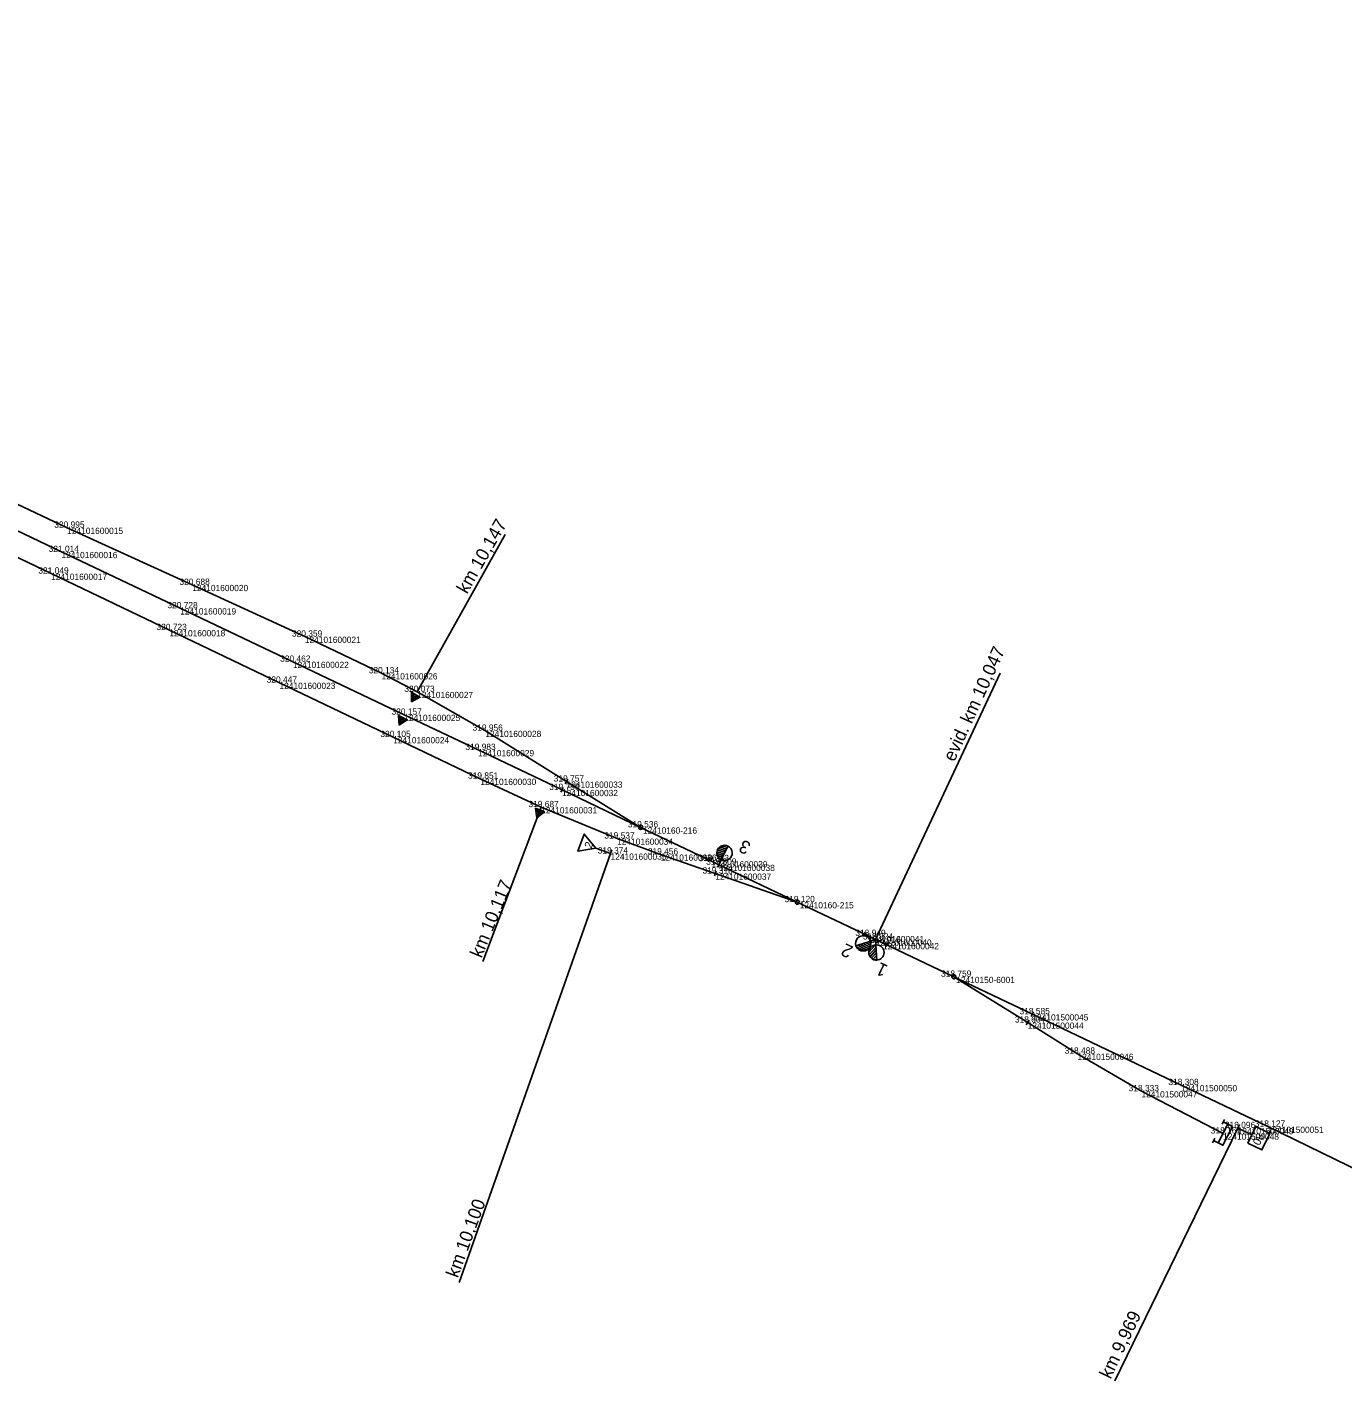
# Model space of a CAD drawing. Extents: x -616949 to -607976, y -1164436 to -1159224.
# Drawn here: x -616071.3 to -615819.4, y -1159974.5 to -1159715.2 of the extents above; entities that cross this region are included whole.
import ezdxf

# ---------------------------------------------------------------- set-up
doc = ezdxf.new("R2010")
doc.units = 0
for name, color, linetype in [('Vrstva 1', 7, 'Continuous'), ('Vrstva 15', 7, 'Continuous'), ('Vrstva 2', 7, 'Continuous'), ('Vrstva 3', 7, 'Continuous'), ('Vrstva 5', 7, 'Continuous'), ('Vrstva 60', 7, 'Continuous'), ('Vrstva 61', 7, 'Continuous')]:
    doc.layers.add(name, color=color, linetype=linetype)

msp = doc.modelspace()

# ---------------------------------------------------------------- linework, layer by layer
at = {"layer": 'Vrstva 1'}
for points in [[(-615908.84, -1159889.93), (-615910.27, -1159889.25), (-615923.84, -1159882.78), (-615939.55, -1159877.3), (-615950.02, -1159873.65), (-615958.35, -1159870.6), (-615972.88, -1159864.59), (-615984.54, -1159859.14), (-616001.22, -1159851.17), (-616023, -1159840.76), (-616044.09, -1159830.68), (-616066.72, -1159819.87), (-616088.67, -1159809.39), (-616107.11, -1159800.11), (-616112.99, -1159796.93), (-616128.47, -1159787.95), (-616137.63, -1159782.18), (-616142.77, -1159778.79), (-616153.3, -1159771.43), (-616169.07, -1159759.51), (-616184.52, -1159746.63), (-616200.28, -1159732.04), (-616217.13, -1159716.1), (-616218.05, -1159715.21)], [(-615938.86, -1159875.61), (-615940.27, -1159874.93), (-615953.84, -1159868.46), (-615968.03, -1159859.68), (-615983.58, -1159849.96), (-615996.64, -1159842.51), (-616003.45, -1159838.94), (-616018.15, -1159831.94), (-616039.7, -1159822.03), (-616063.66, -1159811.08), (-616084.21, -1159801.41), (-616107.46, -1159789.34), (-616114.32, -1159785.46), (-616128.35, -1159776.94), (-616131.48, -1159774.93), (-616137.2, -1159771.16), (-616148.09, -1159763.54), (-616163.09, -1159752.06), (-616177.88, -1159739.63), (-616193.93, -1159724.96), (-616196.14, -1159722.89)], [(-615938.86, -1159875.61), (-615940.27, -1159874.93), (-615953.84, -1159868.46), (-615968.9, -1159861.28), (-615984.95, -1159853.64), (-615999.1, -1159846.89), (-616020.43, -1159836.75), (-616042.01, -1159826.5), (-616064.75, -1159815.71), (-616086.42, -1159805.34)], [(-615908.84, -1159889.93), (-615910.27, -1159889.25), (-615923.84, -1159882.78), (-615938.86, -1159875.61)], [(-615842.33, -1159927.08), (-615857.95, -1159918.98), (-615870.19, -1159911.8), (-615879.73, -1159905.83), (-615893.87, -1159897.07), (-615907.43, -1159890.61), (-615908.84, -1159889.93)], [(-615813.21, -1159935.78), (-615833.77, -1159925.77), (-615850.34, -1159917.81), (-615878.83, -1159904.24), (-615893.87, -1159897.07), (-615907.43, -1159890.61), (-615908.84, -1159889.93)]]:
    msp.add_lwpolyline(points, dxfattribs=at)
at = {"layer": 'Vrstva 15'}
for p, q in [((-615841.41, -1159925.31), (-615843.25, -1159928.86)), ((-615842.06, -1159924.4), (-615842.52, -1159925.29)), ((-615843.91, -1159927.95), (-615844.37, -1159928.84))]:
    msp.add_line(p, q, dxfattribs=at)
msp.add_lwpolyline([(-615844.14, -1159928.4), (-615842.36, -1159929.32), (-615840.52, -1159925.77), (-615842.29, -1159924.85)], dxfattribs=at)
at = {"layer": 'Vrstva 2'}
for p, q in [((-615908.84, -1159889.93), (-615885.02, -1159838.94)), ((-615968.29, -1159860.1), (-615967.76, -1159859.26)), ((-615953.84, -1159868.46), (-615968.03, -1159859.68)), ((-615968.68, -1159860.83), (-615969.12, -1159861.73)), ((-615939.24, -1159873.44), (-615937.54, -1159872.84)), ((-615939.21, -1159873.03), (-615937.31, -1159872.35)), ((-615939.17, -1159873.82), (-615937.77, -1159873.32)), ((-615939.01, -1159872.55), (-615937.34, -1159871.96)), ((-615938.41, -1159874.67), (-615937.15, -1159872.03)), ((-615939.07, -1159876.06), (-615938.64, -1159875.16)), ((-615939, -1159874.16), (-615938, -1159873.81)), ((-615938.41, -1159874.67), (-615938.86, -1159875.61)), ((-615938.72, -1159874.47), (-615938.23, -1159874.29)), ((-615939.71, -1159877.77), (-615939.38, -1159876.82)), ((-615909.83, -1159890.24), (-615912.63, -1159891.12)), ((-615910.98, -1159892.12), (-615912.55, -1159891.31)), ((-615910.5, -1159891.95), (-615912.28, -1159891.02)), ((-615910.17, -1159891.69), (-615911.77, -1159890.86)), ((-615909.94, -1159891.38), (-615911.26, -1159890.69)), ((-615909.81, -1159891.02), (-615910.75, -1159890.53)), ((-615909.77, -1159890.61), (-615910.23, -1159890.37)), ((-615908.89, -1159890.97), (-615910.15, -1159892.39)), ((-615908.75, -1159891.38), (-615910.08, -1159892.88)), ((-615909.83, -1159890.24), (-615908.84, -1159889.93)), ((-615908.78, -1159890.96), (-615908.84, -1159889.93)), ((-615908.6, -1159893.88), (-615908.78, -1159890.96)), ((-615908.72, -1159891.91), (-615909.9, -1159893.24)), ((-615908.69, -1159892.44), (-615909.64, -1159893.52)), ((-615908.66, -1159892.97), (-615909.33, -1159893.73)), ((-615908.62, -1159893.5), (-615908.94, -1159893.85)), ((-615893.87, -1159897.07), (-615879.73, -1159905.83)), ((-615879.05, -1159904.69), (-615878.62, -1159903.79)), ((-615880, -1159906.25), (-615879.47, -1159905.41))]:
    msp.add_line(p, q, dxfattribs=at)
for points in [[(-615938.86, -1159875.61), (-615940.27, -1159874.93), (-615953.84, -1159868.46), (-615968.9, -1159861.28)], [(-615941.26, -1159874.75), (-615940.27, -1159874.93), (-615941.03, -1159874.28)], [(-615908.84, -1159889.93), (-615910.27, -1159889.25), (-615923.84, -1159882.78), (-615938.86, -1159875.61)], [(-615923.84, -1159882.78), (-615939.55, -1159877.3)], [(-615911.26, -1159889.06), (-615910.27, -1159889.25), (-615911.03, -1159888.6)], [(-615908.84, -1159889.93), (-615907.43, -1159890.61), (-615893.87, -1159897.07), (-615878.83, -1159904.24)], [(-615906.45, -1159890.79), (-615907.43, -1159890.61), (-615906.68, -1159891.26)]]:
    msp.add_lwpolyline(points, dxfattribs=at)
for centre, radius in [((-615953.84, -1159868.46), 0.4), ((-615923.84, -1159882.78), 0.4), ((-615908.69, -1159892.42), 1.46), ((-615893.87, -1159897.07), 0.4)]:
    msp.add_circle(centre, radius, dxfattribs=at)
for centre, start, end in [((-615937.78, -1159873.35), 64.5185, 244.4794), ((-615937.77, -1159873.36), 244.2642, 64.7337), ((-615911.23, -1159890.68), 17.2943, 197.7638), ((-615911.23, -1159890.68), 197.5486, 17.5095), ((-615908.69, -1159892.42), 93.53, 273.4908)]:
    msp.add_arc(centre, 1.46, start, end, dxfattribs=at)
at = {"layer": 'Vrstva 3'}
for p, q in [((-615996.64, -1159842.51), (-615979.79, -1159812.35)), ((-615997.33, -1159842.82), (-615997.74, -1159842.93)), ((-615996.95, -1159843.04), (-615997.74, -1159843.25)), ((-615996.58, -1159843.25), (-615997.74, -1159843.57)), ((-615996.2, -1159843.47), (-615997.74, -1159843.89)), ((-615997.01, -1159844), (-615997.73, -1159844.21)), ((-615999.77, -1159847.25), (-616000.17, -1159847.4)), ((-615999.37, -1159847.44), (-616000.15, -1159847.72)), ((-615998.99, -1159847.63), (-616000.13, -1159848.03)), ((-615998.59, -1159847.82), (-616000.1, -1159848.35)), ((-615999.36, -1159848.41), (-616000.07, -1159848.67)), ((-615972.88, -1159864.59), (-615984.07, -1159894.16)), ((-615973.52, -1159864.99), (-615973.92, -1159865.15)), ((-615973.12, -1159865.15), (-615973.88, -1159865.47)), ((-615972.72, -1159865.32), (-615973.84, -1159865.78)), ((-615972.32, -1159865.49), (-615973.79, -1159866.1)), ((-615973.06, -1159866.12), (-615973.75, -1159866.41))]:
    msp.add_line(p, q, dxfattribs=at)
for points in [[(-615997.74, -1159844.43), (-615996.14, -1159843.5), (-615997.75, -1159842.58)], [(-616000.05, -1159848.89), (-615998.53, -1159847.85), (-616000.2, -1159847.05)], [(-615973.72, -1159866.64), (-615972.26, -1159865.51), (-615973.97, -1159864.8)]]:
    msp.add_lwpolyline(points, close=True, dxfattribs=at)
at = {"layer": 'Vrstva 5'}
for p, q in [((-615959.6, -1159873.47), (-615988.58, -1159955.59)), ((-615959.86, -1159874.18), (-615959.35, -1159872.77)), ((-615839.19, -1159925.36), (-615839.84, -1159926.71)), ((-615839.52, -1159926.04), (-615863.05, -1159974.46)), ((-615839.52, -1159926.04), (-615836.81, -1159927.34))]:
    msp.add_line(p, q, dxfattribs=at)
msp.add_lwpolyline([(-615959.6, -1159873.47), (-615962.42, -1159872.44), (-615965.84, -1159873.05), (-615964.64, -1159869.76), (-615962.42, -1159872.44)], dxfattribs=at)
msp.add_lwpolyline([(-615837.57, -1159928.91), (-615836.06, -1159925.76), (-615833.35, -1159927.06), (-615834.87, -1159930.21)], close=True, dxfattribs=at)
at = {"layer": 'Vrstva 60'}
for p, q in [((-616063.66, -1159811.08), (-616063.66, -1159811.08)), ((-616064.75, -1159815.71), (-616064.75, -1159815.71)), ((-616066.72, -1159819.87), (-616066.72, -1159819.87)), ((-616039.7, -1159822.03), (-616039.7, -1159822.03)), ((-616042.01, -1159826.5), (-616042.01, -1159826.5)), ((-616044.09, -1159830.68), (-616044.09, -1159830.68)), ((-616018.15, -1159831.94), (-616018.15, -1159831.94)), ((-616020.43, -1159836.75), (-616020.43, -1159836.75)), ((-616003.45, -1159838.94), (-616003.45, -1159838.94)), ((-616023, -1159840.76), (-616023, -1159840.76)), ((-615996.64, -1159842.51), (-615996.64, -1159842.51)), ((-615999.1, -1159846.89), (-615999.1, -1159846.89)), ((-615983.58, -1159849.96), (-615983.58, -1159849.96)), ((-616001.22, -1159851.17), (-616001.22, -1159851.17)), ((-615984.95, -1159853.64), (-615984.95, -1159853.64)), ((-615984.54, -1159859.14), (-615984.54, -1159859.14)), ((-615968.03, -1159859.68), (-615968.03, -1159859.68)), ((-615968.9, -1159861.28), (-615968.9, -1159861.28)), ((-615972.88, -1159864.59), (-615972.88, -1159864.59)), ((-615953.84, -1159868.46), (-615953.84, -1159868.46)), ((-615958.35, -1159870.6), (-615958.35, -1159870.6)), ((-615959.6, -1159873.47), (-615959.6, -1159873.47)), ((-615950.02, -1159873.65), (-615950.02, -1159873.65)), ((-615940.27, -1159874.93), (-615940.27, -1159874.93)), ((-615938.86, -1159875.61), (-615938.86, -1159875.61)), ((-615939.55, -1159877.3), (-615939.55, -1159877.3)), ((-615923.84, -1159882.78), (-615923.84, -1159882.78)), ((-615910.27, -1159889.25), (-615910.27, -1159889.25)), ((-615908.84, -1159889.93), (-615908.84, -1159889.93)), ((-615907.43, -1159890.61), (-615907.43, -1159890.61)), ((-615893.87, -1159897.07), (-615893.87, -1159897.07)), ((-615878.83, -1159904.24), (-615878.83, -1159904.24)), ((-615879.73, -1159905.83), (-615879.73, -1159905.83)), ((-615870.19, -1159911.8), (-615870.19, -1159911.8)), ((-615857.95, -1159918.98), (-615857.95, -1159918.98)), ((-615850.34, -1159917.81), (-615850.34, -1159917.81)), ((-615842.33, -1159927.08), (-615842.33, -1159927.08)), ((-615839.52, -1159926.04), (-615839.52, -1159926.04)), ((-615833.77, -1159925.77), (-615833.77, -1159925.77))]:
    msp.add_line(p, q, dxfattribs=at)

# ---------------------------------------------------------------- texts
at = {"layer": 'Vrstva 2'}
for s, rotation, p in [('evid. km 10,047', 65.5113, (-615893.78, -1159856.04)), ('3', 154.4989, (-615932.54, -1159871.54)), ('2', 154.2864, (-615912.96, -1159891.39)), ('1', 154.5131, (-615906.32, -1159895.01))]:
    msp.add_text(s, height=2.5, rotation=rotation, dxfattribs=at).set_placement(p)
at = {"layer": 'Vrstva 3'}
for s, rotation, p in [('km 10,147', 60.2977, (-615987.09, -1159823.9)), ('km 10,117', 67.5074, (-615984.33, -1159893.61))]:
    msp.add_text(s, height=2.5, rotation=rotation, dxfattribs=at).set_placement(p)
at = {"layer": 'Vrstva 5'}
for s, height, rotation, p in [('2', 1.5, 69.8718, (-615963.27, -1159872.59)), ('80', 1.5, 244.341, (-615835.74, -1159926.84)), ('km 10,100', 2.5, 69.8718, (-615988.86, -1159954.86)), ('km 9,969', 2.5, 64.341, (-615863.88, -1159974.22))]:
    msp.add_text(s, height=height, rotation=rotation, dxfattribs=at).set_placement(p)
at = {"layer": 'Vrstva 60'}
for s, p in [('124101600015', (-616063.66, -1159812.28)), ('124101600016', (-616064.75, -1159816.91)), ('124101600017', (-616066.72, -1159821.07)), ('124101600020', (-616039.7, -1159823.23)), ('124101600019', (-616042.01, -1159827.7)), ('124101600018', (-616044.09, -1159831.88)), ('124101600021', (-616018.15, -1159833.14)), ('124101600022', (-616020.43, -1159837.95)), ('124101600026', (-616003.45, -1159840.14)), ('124101600023', (-616023, -1159841.96)), ('124101600027', (-615996.64, -1159843.71)), ('124101600025', (-615999.1, -1159848.09)), ('124101600028', (-615983.58, -1159851.16)), ('124101600024', (-616001.22, -1159852.37)), ('124101600029', (-615984.95, -1159854.84)), ('124101600030', (-615984.54, -1159860.34)), ('124101600033', (-615968.03, -1159860.88)), ('124101600032', (-615968.9, -1159862.48)), ('124101600031', (-615972.88, -1159865.79)), (' 12410160-216', (-615953.84, -1159869.66)), ('124101600034', (-615958.35, -1159871.8)), ('124101600035', (-615959.6, -1159874.67)), ('124101600036', (-615950.02, -1159874.85)), ('124101600039', (-615940.27, -1159876.13)), ('124101600038', (-615938.86, -1159876.81)), ('124101600037', (-615939.55, -1159878.5)), (' 12410160-215', (-615923.84, -1159883.98)), ('124101600041', (-615910.27, -1159890.45)), ('124101600040', (-615908.84, -1159891.13)), ('124101600042', (-615907.43, -1159891.81)), (' 12410150-6001', (-615893.87, -1159898.28)), ('124101500045', (-615878.83, -1159905.44)), ('124101500044', (-615879.73, -1159907.03)), ('124101500046', (-615870.19, -1159913)), ('124101500047', (-615857.95, -1159920.18)), ('124101500050', (-615850.34, -1159919.01)), ('124101500048', (-615842.33, -1159928.28)), ('124101500049', (-615839.52, -1159927.24)), ('124101500051', (-615833.77, -1159926.97))]:
    msp.add_text(s, height=1.2, dxfattribs=at).set_placement(p)
at = {"layer": 'Vrstva 61'}
for s, p in [('320.995', (-616066.12, -1159811.08)), ('321.014', (-616067.2, -1159815.71)), ('321.049', (-616069.17, -1159819.87)), ('320.688', (-616042.15, -1159822.03)), ('320.728', (-616044.46, -1159826.5)), ('320.723', (-616046.55, -1159830.68)), ('320.359', (-616020.61, -1159831.94)), ('320.462', (-616022.87, -1159836.75)), ('320.447', (-616025.45, -1159840.76)), ('320.134', (-616005.91, -1159838.94)), ('320.073', (-615999.09, -1159842.51)), ('320.157', (-616001.55, -1159846.89)), ('320.105', (-616003.68, -1159851.17)), ('319.956', (-615986.03, -1159849.96)), ('319.983', (-615987.4, -1159853.64)), ('319.851', (-615986.9, -1159859.14)), ('319.750', (-615971.35, -1159861.28)), ('319.757', (-615970.48, -1159859.68)), ('319.687', (-615975.33, -1159864.59)), ('319.536', (-615956.29, -1159868.46)), ('319.537', (-615960.8, -1159870.6)), ('319.374', (-615962.06, -1159873.47)), ('319.456', (-615952.47, -1159873.65)), ('319.343', (-615942.73, -1159874.93)), ('319.318', (-615942, -1159877.3)), ('319.309', (-615941.31, -1159875.61)), ('319.120', (-615926.29, -1159882.78)), ('318.949', (-615912.73, -1159889.25)), ('318.924', (-615911.29, -1159889.93)), ('318.916', (-615909.89, -1159890.61)), ('318.759', (-615896.32, -1159897.07)), ('318.604', (-615882.18, -1159905.83)), ('318.585', (-615881.29, -1159904.24)), ('318.488', (-615872.64, -1159911.8)), ('318.308', (-615852.79, -1159917.81)), ('318.333', (-615860.4, -1159918.98)), ('318.096', (-615841.97, -1159926.04)), ('318.127', (-615836.22, -1159925.77)), ('318.161', (-615844.68, -1159927.08))]:
    msp.add_text(s, height=1.2, dxfattribs=at).set_placement(p)

doc.saveas('drawing.dxf')
